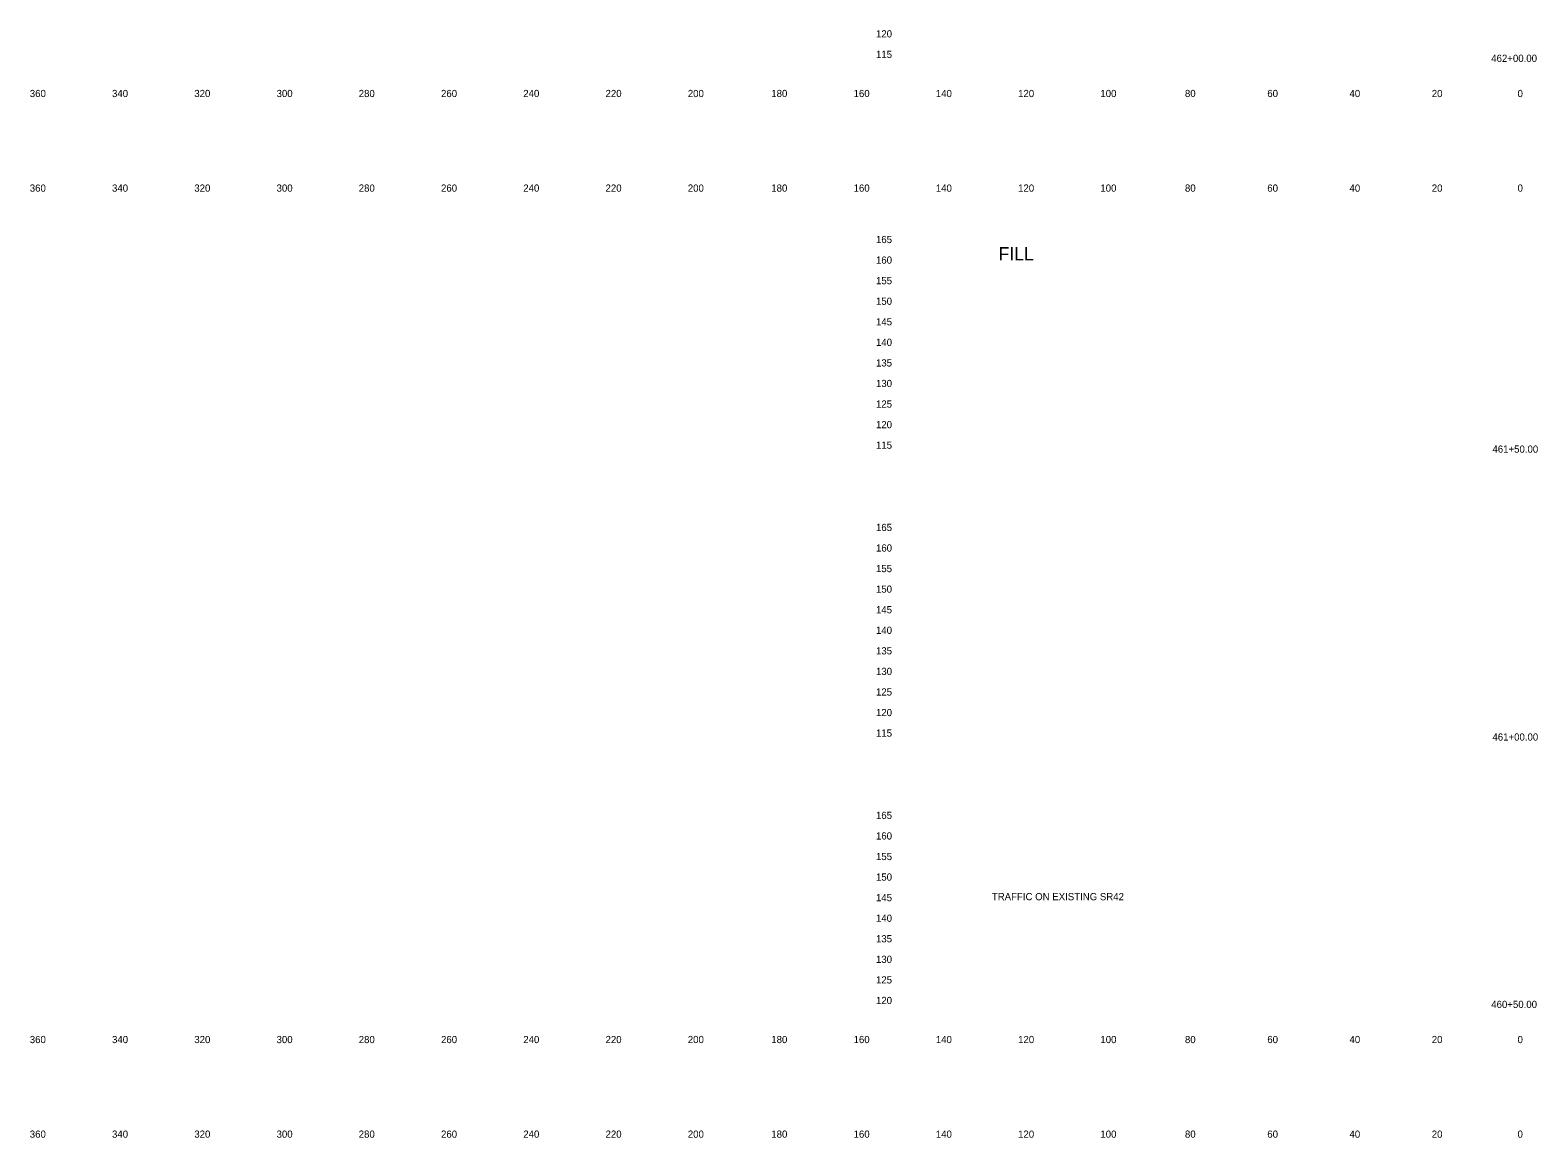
# Model space of a CAD drawing. Extents: x 21281 to 22024, y 6472 to 15198.
# Drawn here: x 21280.5 to 21647, y 7832.3 to 8101.6 of the extents above; entities that cross this region are included whole.
import ezdxf

# ---------------------------------------------------------------- set-up
doc = ezdxf.new("R2010")
doc.units = 0
for name, color, linetype in [('XS_SHEET_LABELS_ELEVATION', 7, 'Continuous'), ('XS_SHEET_LABELS_OFFSET', 7, 'Continuous'), ('XS_SHEET_LABELS_STATION', 7, 'Continuous')]:
    doc.layers.add(name, color=color, linetype=linetype)

msp = doc.modelspace()

# ---------------------------------------------------------------- texts
at = {"layer": 'XS_SHEET_LABELS_ELEVATION'}
for s, p in [('  120  ', (21484.84, 8099.84)), ('  115  ', (21484.84, 8094.84)), ('  165  ', (21484.84, 8049.84)), ('  160  ', (21484.84, 8044.84)), ('  155  ', (21484.84, 8039.84)), ('  150  ', (21484.84, 8034.84)), ('  145  ', (21484.84, 8029.84)), ('  140  ', (21484.84, 8024.84)), ('  135  ', (21484.84, 8019.84)), ('  130  ', (21484.84, 8014.84)), ('  125  ', (21484.84, 8009.84)), ('  120  ', (21484.84, 8004.84)), ('  115  ', (21484.84, 7999.84)), ('  165  ', (21484.84, 7979.84)), ('  160  ', (21484.84, 7974.84)), ('  155  ', (21484.84, 7969.84)), ('  150  ', (21484.84, 7964.84)), ('  145  ', (21484.84, 7959.84)), ('  140  ', (21484.84, 7954.84)), ('  135  ', (21484.84, 7949.84)), ('  130  ', (21484.84, 7944.84)), ('  125  ', (21484.84, 7939.84)), ('  120  ', (21484.84, 7934.84)), ('  115  ', (21484.84, 7929.84)), ('  165  ', (21484.84, 7909.84)), ('  160  ', (21484.84, 7904.84)), ('  155  ', (21484.84, 7899.84)), ('  150  ', (21484.84, 7894.84)), ('  145  ', (21484.84, 7889.84)), ('  140  ', (21484.84, 7884.84)), ('  135  ', (21484.84, 7879.84)), ('  130  ', (21484.84, 7874.84)), ('  125  ', (21484.84, 7869.84)), ('  120  ', (21484.84, 7864.84))]:
    msp.add_text(s, height=1.75, dxfattribs=at).set_placement(p)
at = {"layer": 'XS_SHEET_LABELS_OFFSET'}
for s, height, p in [('  360  ', 1.75, (21279.14, 8085.34)), ('  340  ', 1.75, (21299.13, 8085.34)), ('  320  ', 1.75, (21319.13, 8085.34)), ('  300  ', 1.75, (21339.13, 8085.34)), ('  280  ', 1.75, (21359.1, 8085.34)), ('  260  ', 1.75, (21379.11, 8085.34)), ('  240  ', 1.75, (21399.1, 8085.34)), ('  220  ', 1.75, (21419.1, 8085.34)), ('  200  ', 1.75, (21439.1, 8085.34)), ('  180  ', 1.75, (21459.39, 8085.34)), ('  160  ', 1.75, (21479.4, 8085.34)), ('  140  ', 1.75, (21499.39, 8085.34)), ('  120  ', 1.75, (21519.39, 8085.34)), ('  100  ', 1.75, (21539.39, 8085.34)), ('  80  ', 1.75, (21559.95, 8085.34)), ('  60  ', 1.75, (21579.97, 8085.34)), ('  40  ', 1.75, (21599.95, 8085.34)), ('  20  ', 1.75, (21619.95, 8085.34)), ('  0  ', 1.75, (21640.81, 8085.34)), ('  0  ', 1.75, (21640.81, 8085.34)), ('  360  ', 1.75, (21279.14, 8062.34)), ('  340  ', 1.75, (21299.13, 8062.34)), ('  320  ', 1.75, (21319.13, 8062.34)), ('  300  ', 1.75, (21339.13, 8062.34)), ('  280  ', 1.75, (21359.1, 8062.34)), ('  260  ', 1.75, (21379.11, 8062.34)), ('  240  ', 1.75, (21399.1, 8062.34)), ('  220  ', 1.75, (21419.1, 8062.34)), ('  200  ', 1.75, (21439.1, 8062.34)), ('  180  ', 1.75, (21459.39, 8062.34)), ('  160  ', 1.75, (21479.4, 8062.34)), ('  140  ', 1.75, (21499.39, 8062.34)), ('  120  ', 1.75, (21519.39, 8062.34)), ('  100  ', 1.75, (21539.39, 8062.34)), ('  80  ', 1.75, (21559.95, 8062.34)), ('  60  ', 1.75, (21579.97, 8062.34)), ('  40  ', 1.75, (21599.95, 8062.34)), ('  20  ', 1.75, (21619.95, 8062.34)), ('  0  ', 1.75, (21640.81, 8062.34)), ('  0  ', 1.75, (21640.81, 8062.34)), ('FILL', 3.222, (21515.91, 8045.64)), ('  360  ', 1.75, (21279.14, 7855.34)), ('  340  ', 1.75, (21299.13, 7855.34)), ('  320  ', 1.75, (21319.13, 7855.34)), ('  300  ', 1.75, (21339.13, 7855.34)), ('  280  ', 1.75, (21359.1, 7855.34)), ('  260  ', 1.75, (21379.11, 7855.34)), ('  240  ', 1.75, (21399.1, 7855.34)), ('  220  ', 1.75, (21419.1, 7855.34)), ('  200  ', 1.75, (21439.1, 7855.34)), ('  180  ', 1.75, (21459.39, 7855.34)), ('  160  ', 1.75, (21479.4, 7855.34)), ('  140  ', 1.75, (21499.39, 7855.34)), ('  120  ', 1.75, (21519.39, 7855.34)), ('  100  ', 1.75, (21539.39, 7855.34)), ('  80  ', 1.75, (21559.95, 7855.34)), ('  60  ', 1.75, (21579.97, 7855.34)), ('  40  ', 1.75, (21599.95, 7855.34)), ('  20  ', 1.75, (21619.95, 7855.34)), ('  0  ', 1.75, (21640.81, 7855.34)), ('  0  ', 1.75, (21640.81, 7855.34)), ('  360  ', 1.75, (21279.14, 7832.34)), ('  340  ', 1.75, (21299.13, 7832.34)), ('  320  ', 1.75, (21319.13, 7832.34)), ('  300  ', 1.75, (21339.13, 7832.34)), ('  280  ', 1.75, (21359.1, 7832.34)), ('  260  ', 1.75, (21379.11, 7832.34)), ('  240  ', 1.75, (21399.1, 7832.34)), ('  220  ', 1.75, (21419.1, 7832.34)), ('  200  ', 1.75, (21439.1, 7832.34)), ('  180  ', 1.75, (21459.39, 7832.34)), ('  160  ', 1.75, (21479.4, 7832.34)), ('  140  ', 1.75, (21499.39, 7832.34)), ('  120  ', 1.75, (21519.39, 7832.34)), ('  100  ', 1.75, (21539.39, 7832.34)), ('  80  ', 1.75, (21559.95, 7832.34)), ('  60  ', 1.75, (21579.97, 7832.34)), ('  40  ', 1.75, (21599.95, 7832.34)), ('  20  ', 1.75, (21619.95, 7832.34)), ('  0  ', 1.75, (21640.81, 7832.34)), ('  0  ', 1.75, (21640.81, 7832.34))]:
    msp.add_text(s, height=height, dxfattribs=at).set_placement(p)
at = {"layer": 'XS_SHEET_LABELS_STATION'}
for s, p in [('  462+00.00  ', (21634.41, 8093.89)), ('  461+50.00  ', (21634.7, 7998.89)), ('  461+00.00  ', (21634.7, 7928.89)), ('TRAFFIC ON EXISTING SR42', (21514.31, 7890.08)), ('  460+50.00  ', (21634.41, 7863.89))]:
    msp.add_text(s, height=1.75, dxfattribs=at).set_placement(p)

doc.saveas('drawing.dxf')
